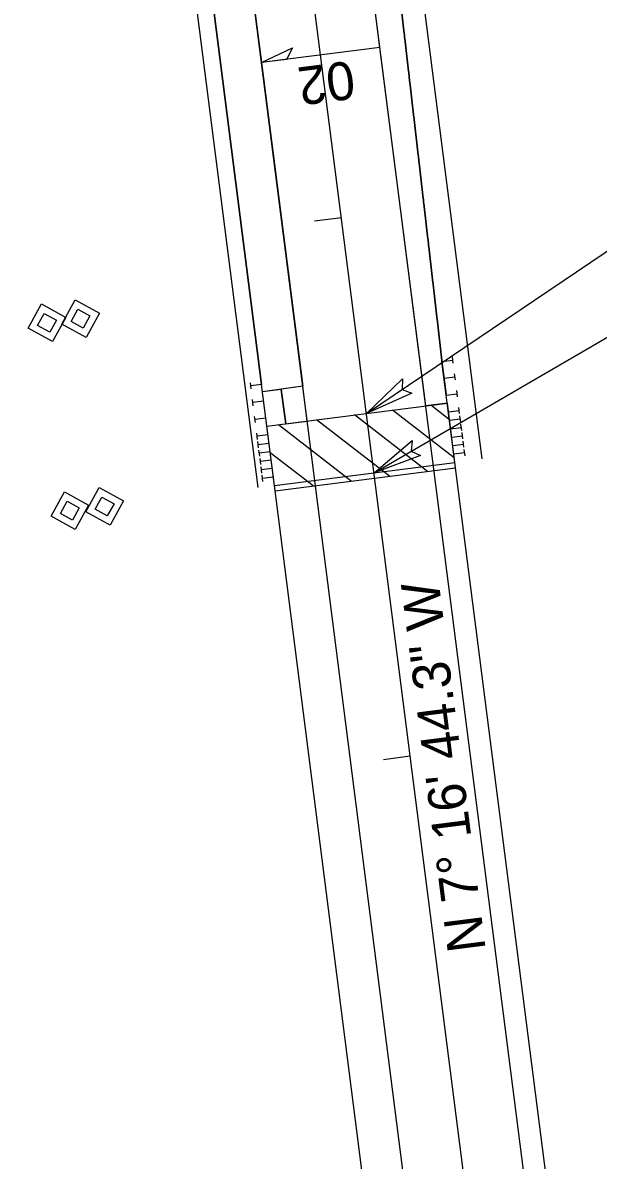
# Model space of a CAD drawing. Extents: x 2167182 to 2168576, y 842635 to 844493.
# Drawn here: x 2167981.8 to 2168087.7, y 843360.4 to 843569.9 of the extents above; entities that cross this region are included whole.
import ezdxf

# ---------------------------------------------------------------- set-up
doc = ezdxf.new("R2010")
doc.units = 0
for name, color, linetype in [('Prop Approach Slab', 7, 'Continuous'), ('Prop Approach Slab Hatching', 7, 'Continuous'), ('Prop Conc Shoulder Berm Gutter', 7, 'Continuous'), ('Prop Dimension', 7, 'Continuous'), ('Prop EOT', 7, 'Continuous'), ('Prop Guardrail', 7, 'Continuous'), ('Prop Horizontal Alignment', 7, 'Continuous'), ('Prop Horizontal Alignment Direction Label', 7, 'Continuous'), ('Prop Horizontal Alignment Tick Small', 7, 'Continuous'), ('Prop Paved Shoulder', 7, 'Continuous'), ('Prop Roadway Bridge', 7, 'Continuous'), ('Prop ROW Marker CELL', 7, 'Continuous'), ('Prop ROW Permanent Easement CELL', 7, 'Continuous'), ('Prop Shade Light', 7, 'Continuous'), ('Prop Structure Anchor Unit CELL', 7, 'Continuous'), ('Prop Superelevation  Arrow CELL', 7, 'Continuous'), ('Prop Superelevation Label', 7, 'Continuous'), ('Prop Terminator CELL', 7, 'Continuous'), ('Scratch_Level_1', 7, 'Continuous')]:
    doc.layers.add(name, color=color, linetype=linetype)

# ---------------------------------------------------------------- blocks, each defined once
blk = doc.blocks.new('ROW Marker Permanent Easement-E')
at = {"layer": 'Prop ROW Marker CELL'}
blk.add_line((0, 0), (0, 0), dxfattribs=at)
at = {"layer": 'Prop ROW Permanent Easement CELL'}
for points in [[(0, 0.072), (0.072, 0), (0, -0.072), (-0.072, 0)], [(0, 0.036), (0.036, 0), (0, -0.036), (-0.036, 0)]]:
    blk.add_lwpolyline(points, close=True, dxfattribs=at)

msp = doc.modelspace()

# ---------------------------------------------------------------- linework, layer by layer
at = {"layer": 'Prop Approach Slab'}
for p, q in [((2168026.74, 843495.59), (2168059.97, 843499.84)), ((2168061.49, 843487.93), (2168059.97, 843499.84)), ((2168028.26, 843483.69), (2168026.74, 843495.59)), ((2168028.26, 843483.69), (2168061.49, 843487.93))]:
    msp.add_line(p, q, dxfattribs=at)
at = {"layer": 'Prop Approach Slab Hatching'}
for p, q in [((2168060.36, 843496.79), (2168056.92, 843499.45)), ((2168056.31, 843487.27), (2168042.89, 843497.66)), ((2168061.25, 843489.77), (2168049.9, 843498.55)), ((2168042.28, 843485.48), (2168028.86, 843495.86)), ((2168049.3, 843486.38), (2168035.87, 843496.76)), ((2168035.27, 843484.59), (2168027.36, 843490.7))]:
    msp.add_line(p, q, dxfattribs=at)
at = {"layer": 'Prop Conc Shoulder Berm Gutter'}
msp.add_line((2168030.21, 843496.04), (2168029.4, 843502.34), dxfattribs=at)
at = {"layer": 'Prop Dimension'}
for points in [[(2168045.09, 843497.94), (2168145.81, 843565.86)], [(2168046.48, 843487.03), (2168147.89, 843545.97)]]:
    msp.add_lwpolyline(points, dxfattribs=at)
at = {"layer": 'Prop EOT'}
for p, q in [((2168087.65, 843251.57), (2168041.48, 843612.96)), ((2168065.82, 843248.78), (2168019.66, 843610.17))]:
    msp.add_line(p, q, dxfattribs=at)
at = {"layer": 'Prop Guardrail'}
for p, q in [((2168012.22, 843609.22), (2168025.75, 843503.28)), ((2168061.36, 843488.93), (2168058.98, 843507.52)), ((2168028.13, 843484.68), (2168025.75, 843503.28))]:
    msp.add_line(p, q, dxfattribs=at)
for points in [[(2168052.78, 843561.34), (2168052.7, 843562.07), (2168052.61, 843562.79), (2168052.53, 843563.52), (2168052.45, 843564.25), (2168052.36, 843564.98), (2168052.28, 843565.7), (2168052.2, 843566.43), (2168052.11, 843567.16), (2168052.03, 843567.88), (2168051.94, 843568.61), (2168051.86, 843569.34), (2168051.78, 843570.07), (2168051.69, 843570.79), (2168051.61, 843571.52), (2168051.53, 843572.25), (2168051.44, 843572.98), (2168051.36, 843573.7), (2168051.27, 843574.43), (2168051.19, 843575.16), (2168051.11, 843575.88), (2168051.02, 843576.61), (2168050.94, 843577.34), (2168050.85, 843578.07), (2168050.77, 843578.79), (2168050.69, 843579.52), (2168050.6, 843580.25), (2168050.52, 843580.97), (2168050.44, 843581.7), (2168050.35, 843582.43), (2168050.27, 843583.16), (2168050.18, 843583.88), (2168050.1, 843584.61), (2168050.02, 843585.34), (2168049.93, 843586.07), (2168049.85, 843586.79), (2168049.77, 843587.52), (2168049.68, 843588.25), (2168049.6, 843588.97), (2168049.51, 843589.7), (2168049.43, 843590.43), (2168049.35, 843591.16), (2168049.26, 843591.88), (2168049.18, 843592.61), (2168049.09, 843593.34), (2168049.01, 843594.06), (2168048.93, 843594.79), (2168048.84, 843595.52), (2168048.76, 843596.25), (2168048.68, 843596.97), (2168048.59, 843597.7), (2168048.51, 843598.43), (2168048.42, 843599.16), (2168048.34, 843599.88), (2168048.26, 843600.61), (2168048.17, 843601.34), (2168048.09, 843602.06), (2168048.01, 843602.79), (2168047.92, 843603.52), (2168047.84, 843604.25), (2168047.75, 843604.97), (2168047.67, 843605.7), (2168047.59, 843606.43), (2168047.5, 843607.15), (2168047.42, 843607.88), (2168047.33, 843608.61), (2168047.25, 843609.34), (2168047.17, 843610.06), (2168047.08, 843610.79), (2168047, 843611.52), (2168046.92, 843612.25), (2168046.83, 843612.97), (2168046.75, 843613.7), (2168046.66, 843614.44), (2168046.58, 843615.18)], [(2168058.98, 843507.52), (2168058.9, 843508.25), (2168058.82, 843508.98), (2168058.73, 843509.71), (2168058.65, 843510.43), (2168058.56, 843511.16), (2168058.48, 843511.89), (2168058.4, 843512.62), (2168058.31, 843513.34), (2168058.23, 843514.07), (2168058.15, 843514.8), (2168058.06, 843515.52), (2168057.98, 843516.25), (2168057.89, 843516.98), (2168057.81, 843517.71), (2168057.73, 843518.43), (2168057.64, 843519.16), (2168057.56, 843519.89), (2168057.48, 843520.62), (2168057.39, 843521.34), (2168057.31, 843522.07), (2168057.22, 843522.8), (2168057.14, 843523.52), (2168057.06, 843524.25), (2168056.97, 843524.98), (2168056.89, 843525.71), (2168056.8, 843526.43), (2168056.72, 843527.16), (2168056.64, 843527.89), (2168056.55, 843528.61), (2168056.47, 843529.34), (2168056.39, 843530.07), (2168056.3, 843530.8), (2168056.22, 843531.52), (2168056.13, 843532.25), (2168056.05, 843532.98), (2168055.97, 843533.71), (2168055.88, 843534.43), (2168055.8, 843535.16), (2168055.72, 843535.89), (2168055.63, 843536.61), (2168055.55, 843537.34), (2168055.46, 843538.07), (2168055.38, 843538.8), (2168055.3, 843539.52), (2168055.21, 843540.25), (2168055.13, 843540.98), (2168055.04, 843541.7), (2168054.96, 843542.43), (2168054.88, 843543.16), (2168054.79, 843543.89), (2168054.71, 843544.61), (2168054.63, 843545.34), (2168054.54, 843546.07), (2168054.46, 843546.8), (2168054.37, 843547.52), (2168054.29, 843548.25), (2168054.21, 843548.98), (2168054.12, 843549.7), (2168054.04, 843550.43), (2168053.96, 843551.16), (2168053.87, 843551.89), (2168053.79, 843552.61), (2168053.7, 843553.34), (2168053.62, 843554.07), (2168053.54, 843554.79), (2168053.45, 843555.52), (2168053.37, 843556.25), (2168053.29, 843556.98), (2168053.2, 843557.7), (2168053.12, 843558.43), (2168053.03, 843559.16), (2168052.95, 843559.89), (2168052.87, 843560.61), (2168052.78, 843561.34)]]:
    msp.add_spline(points, degree=3, dxfattribs=at)
at = {"layer": 'Prop Horizontal Alignment'}
msp.add_line((2168076.73, 843250.17), (2168030.57, 843611.57), dxfattribs=at)
at = {"layer": 'Prop Horizontal Alignment Tick Small'}
for p, q in [((2168040.48, 843533.99), (2168035.52, 843533.36)), ((2168053.15, 843434.8), (2168048.19, 843434.17))]:
    msp.add_line(p, q, dxfattribs=at)
at = {"layer": 'Prop Paved Shoulder'}
msp.add_line((2168029.4, 843502.34), (2168025.93, 843501.89), dxfattribs=at)
at = {"layer": 'Prop Roadway Bridge'}
for p, q in [((2168028.13, 843484.68), (2168061.36, 843488.93)), ((2168078.15, 843357.49), (2168061.36, 843488.93)), ((2168044.92, 843353.25), (2168028.13, 843484.68))]:
    msp.add_line(p, q, dxfattribs=at)
at = {"layer": 'Prop Shade Light'}
for p, q in [((2168025.75, 843503.28), (2168012.22, 843609.22)), ((2168058.98, 843507.52), (2168059.75, 843501.52)), ((2168025.93, 843501.89), (2168025.75, 843503.28)), ((2168033.35, 843502.99), (2168025.93, 843501.89)), ((2168033.35, 843502.99), (2168029.39, 843502.4)), ((2168029.4, 843502.34), (2168030.21, 843496.04)), ((2168034.18, 843496.54), (2168033.35, 843502.99)), ((2168059.97, 843499.84), (2168056, 843499.33)), ((2168059.97, 843499.84), (2168059.97, 843499.84)), ((2168030.21, 843496.04), (2168034.18, 843496.54))]:
    msp.add_line(p, q, dxfattribs=at)
for points in [[(2168056, 843499.33), (2168047.57, 843565.34), (2168044.53, 843589.15), (2168041.48, 843612.96)], [(2168019.66, 843610.17), (2168022.7, 843586.36), (2168025.74, 843562.56), (2168033.35, 843502.99)], [(2168029.39, 843502.4), (2168029.4, 843502.34)], [(2168033.35, 843502.99), (2168033.35, 843502.99)]]:
    msp.add_lwpolyline(points, dxfattribs=at)
for points in [[(2168046.58, 843615.18), (2168046.66, 843614.44), (2168046.75, 843613.7), (2168046.83, 843612.97), (2168046.92, 843612.25), (2168047, 843611.52), (2168047.08, 843610.79), (2168047.17, 843610.06), (2168047.25, 843609.34), (2168047.33, 843608.61), (2168047.42, 843607.88), (2168047.5, 843607.15), (2168047.59, 843606.43), (2168047.67, 843605.7), (2168047.75, 843604.97), (2168047.84, 843604.25), (2168047.92, 843603.52), (2168048.01, 843602.79), (2168048.09, 843602.06), (2168048.17, 843601.34), (2168048.26, 843600.61), (2168048.34, 843599.88), (2168048.42, 843599.16), (2168048.51, 843598.43), (2168048.59, 843597.7), (2168048.68, 843596.97), (2168048.76, 843596.25), (2168048.84, 843595.52), (2168048.93, 843594.79), (2168049.01, 843594.06), (2168049.09, 843593.34), (2168049.18, 843592.61), (2168049.26, 843591.88), (2168049.35, 843591.16), (2168049.43, 843590.43), (2168049.51, 843589.7), (2168049.6, 843588.97), (2168049.68, 843588.25), (2168049.77, 843587.52), (2168049.85, 843586.79), (2168049.93, 843586.07), (2168050.02, 843585.34), (2168050.1, 843584.61), (2168050.18, 843583.88), (2168050.27, 843583.16), (2168050.35, 843582.43), (2168050.44, 843581.7), (2168050.52, 843580.97), (2168050.6, 843580.25), (2168050.69, 843579.52), (2168050.77, 843578.79), (2168050.85, 843578.07), (2168050.94, 843577.34), (2168051.02, 843576.61), (2168051.11, 843575.88), (2168051.19, 843575.16), (2168051.27, 843574.43), (2168051.36, 843573.7), (2168051.44, 843572.98), (2168051.53, 843572.25), (2168051.61, 843571.52), (2168051.69, 843570.79), (2168051.78, 843570.07), (2168051.86, 843569.34), (2168051.94, 843568.61), (2168052.03, 843567.88), (2168052.11, 843567.16), (2168052.2, 843566.43), (2168052.28, 843565.7), (2168052.36, 843564.98), (2168052.45, 843564.25), (2168052.53, 843563.52), (2168052.61, 843562.79), (2168052.7, 843562.07), (2168052.78, 843561.34)], [(2168052.78, 843561.34), (2168052.87, 843560.61), (2168052.95, 843559.89), (2168053.03, 843559.16), (2168053.12, 843558.43), (2168053.2, 843557.7), (2168053.29, 843556.98), (2168053.37, 843556.25), (2168053.45, 843555.52), (2168053.54, 843554.79), (2168053.62, 843554.07), (2168053.7, 843553.34), (2168053.79, 843552.61), (2168053.87, 843551.89), (2168053.96, 843551.16), (2168054.04, 843550.43), (2168054.12, 843549.7), (2168054.21, 843548.98), (2168054.29, 843548.25), (2168054.37, 843547.52), (2168054.46, 843546.8), (2168054.54, 843546.07), (2168054.63, 843545.34), (2168054.71, 843544.61), (2168054.79, 843543.89), (2168054.88, 843543.16), (2168054.96, 843542.43), (2168055.04, 843541.7), (2168055.13, 843540.98), (2168055.21, 843540.25), (2168055.3, 843539.52), (2168055.38, 843538.8), (2168055.46, 843538.07), (2168055.55, 843537.34), (2168055.63, 843536.61), (2168055.72, 843535.89), (2168055.8, 843535.16), (2168055.88, 843534.43), (2168055.97, 843533.71), (2168056.05, 843532.98), (2168056.13, 843532.25), (2168056.22, 843531.52), (2168056.3, 843530.8), (2168056.39, 843530.07), (2168056.47, 843529.34), (2168056.55, 843528.61), (2168056.64, 843527.89), (2168056.72, 843527.16), (2168056.8, 843526.43), (2168056.89, 843525.71), (2168056.97, 843524.98), (2168057.06, 843524.25), (2168057.14, 843523.52), (2168057.22, 843522.8), (2168057.31, 843522.07), (2168057.39, 843521.34), (2168057.48, 843520.62), (2168057.56, 843519.89), (2168057.64, 843519.16), (2168057.73, 843518.43), (2168057.81, 843517.71), (2168057.89, 843516.98), (2168057.98, 843516.25), (2168058.06, 843515.52), (2168058.15, 843514.8), (2168058.23, 843514.07), (2168058.31, 843513.34), (2168058.4, 843512.62), (2168058.48, 843511.89), (2168058.56, 843511.16), (2168058.65, 843510.43), (2168058.73, 843509.71), (2168058.82, 843508.98), (2168058.9, 843508.25), (2168058.98, 843507.52)]]:
    msp.add_spline(points, degree=3, dxfattribs=at)
at = {"layer": 'Prop Structure Anchor Unit CELL'}
for p, q in [((2168061.04, 843507.21), (2168060.9, 843508.35)), ((2168058.98, 843507.52), (2168060.97, 843507.78)), ((2168061.36, 843488.93), (2168058.98, 843507.52)), ((2168059.38, 843504.43), (2168061.36, 843504.68)), ((2168061.44, 843504.11), (2168061.29, 843505.25)), ((2168023.84, 843502.46), (2168023.7, 843503.6)), ((2168025.75, 843503.28), (2168023.77, 843503.03)), ((2168028.13, 843484.68), (2168025.75, 843503.28)), ((2168059.78, 843501.33), (2168061.76, 843501.58)), ((2168061.83, 843501.01), (2168061.69, 843502.15)), ((2168024.24, 843499.36), (2168024.09, 843500.5)), ((2168026.15, 843500.18), (2168024.17, 843499.93)), ((2168024.63, 843496.26), (2168024.49, 843497.4)), ((2168060.17, 843498.23), (2168062.16, 843498.48)), ((2168062.23, 843497.91), (2168062.08, 843499.05)), ((2168062.43, 843496.36), (2168062.28, 843497.5)), ((2168026.55, 843497.08), (2168024.56, 843496.83)), ((2168060.37, 843496.68), (2168062.35, 843496.93)), ((2168060.57, 843495.13), (2168062.55, 843495.38)), ((2168062.62, 843494.81), (2168062.48, 843495.95)), ((2168025.03, 843493.16), (2168024.89, 843494.3)), ((2168026.94, 843493.98), (2168024.96, 843493.73)), ((2168060.77, 843493.58), (2168062.75, 843493.83)), ((2168062.82, 843493.26), (2168062.68, 843494.4)), ((2168025.23, 843491.61), (2168025.08, 843492.75)), ((2168027.14, 843492.43), (2168025.16, 843492.18)), ((2168025.43, 843490.06), (2168025.28, 843491.2)), ((2168060.96, 843492.03), (2168062.95, 843492.28)), ((2168063.02, 843491.71), (2168062.87, 843492.85)), ((2168063.22, 843490.16), (2168063.07, 843491.3)), ((2168027.34, 843490.88), (2168025.35, 843490.63)), ((2168025.62, 843488.51), (2168025.48, 843489.65)), ((2168027.54, 843489.33), (2168025.55, 843489.08)), ((2168061.16, 843490.48), (2168063.15, 843490.73)), ((2168025.82, 843486.96), (2168025.68, 843488.1)), ((2168027.73, 843487.78), (2168025.75, 843487.53)), ((2168026.02, 843485.41), (2168025.88, 843486.55)), ((2168027.93, 843486.23), (2168025.95, 843485.98))]:
    msp.add_line(p, q, dxfattribs=at)
at = {"layer": 'Prop Superelevation  Arrow CELL'}
msp.add_line((2168047.57, 843565.34), (2168025.74, 843562.56), dxfattribs=at)
msp.add_lwpolyline([(2168025.74, 843562.56), (2168031.44, 843565.3), (2168030.33, 843563.14)], close=True, dxfattribs=at)
at = {"layer": 'Prop Terminator CELL'}
for points in [[(2168053.42, 843501.68), (2168045.09, 843497.94), (2168051.7, 843504.32), (2168051.64, 843502.35)], [(2168055.04, 843490.2), (2168046.48, 843487.03), (2168053.51, 843492.95), (2168053.31, 843490.99)]]:
    msp.add_lwpolyline(points, close=True, dxfattribs=at)
at = {"layer": 'Scratch_Level_1'}
for p, q in [((2168050.41, 843614.1), (2168066.32, 843489.56)), ((2168025.15, 843484.3), (2168009.25, 843608.84))]:
    msp.add_line(p, q, dxfattribs=at)

# ---------------------------------------------------------------- block references
at = {"layer": 'Prop Dimension', "xscale": 50.00000000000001, "yscale": 50, "rotation": 106.1236352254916}
for p in [(2167986.26, 843514.64), (2167992.45, 843515.39), (2167996.87, 843480.82), (2167990.47, 843480.04)]:
    msp.add_blockref('ROW Marker Permanent Easement-E', p, dxfattribs=at)

# ---------------------------------------------------------------- texts
at = {"layer": 'Prop Horizontal Alignment Direction Label'}
msp.add_text('N 7%%d 16\' 44.3" W', height=7, rotation=97.279, dxfattribs=at).set_placement((2168067.05, 843399.18))
at = {"layer": 'Prop Superelevation Label'}
msp.add_text('02', height=7, rotation=187.279, dxfattribs=at).set_placement((2168042.43, 843562.92))

doc.saveas('drawing.dxf')
